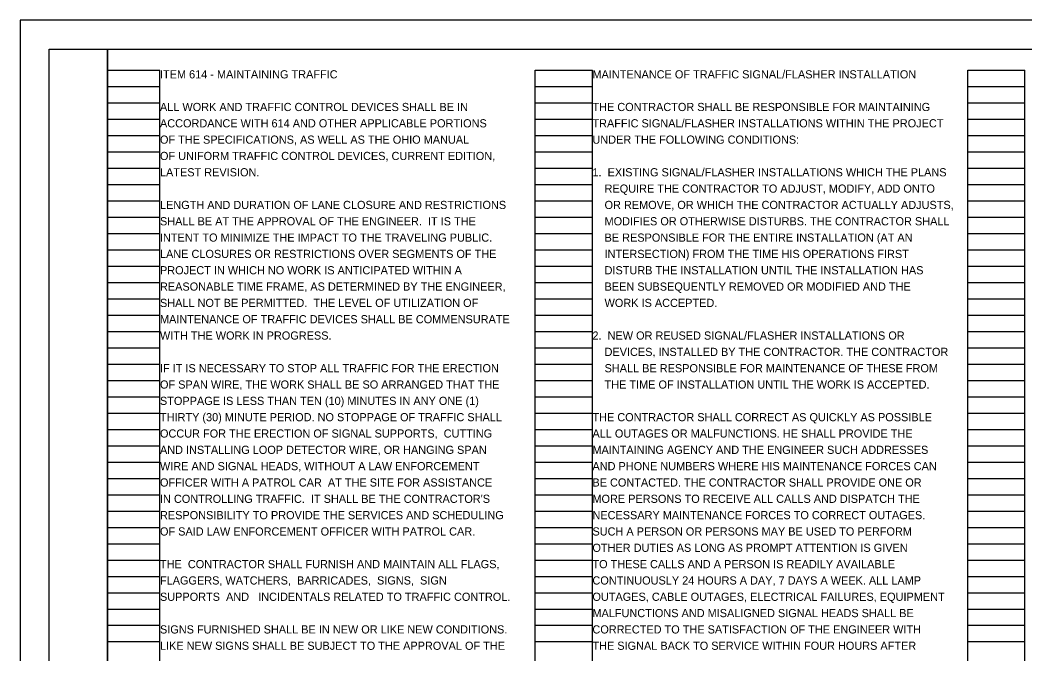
# Model space of a CAD drawing. Extents: x 0 to 34, y 0 to 22.
# Drawn here: x 0 to 17.24, y 11.13 to 22 of the extents above; entities that cross this region are included whole.
import ezdxf

# ---------------------------------------------------------------- set-up
doc = ezdxf.new("R2010")
doc.units = 0
for name, color, linetype in [('SH_Border', 7, 'Continuous'), ('SH_Cut_Line', 7, 'Continuous'), ('SH_Data', 7, 'Continuous'), ('SH_Text', 7, 'Continuous')]:
    doc.layers.add(name, color=color, linetype=linetype)

msp = doc.modelspace()

# ---------------------------------------------------------------- linework, layer by layer
at = {"layer": 'SH_Border'}
for points in [[(0.5, 21.5), (1.5, 21.5), (1.5, 0.5), (0.5, 0.5)], [(1.5, 21.5), (33.5, 21.5), (33.5, 0.5), (1.5, 0.5)]]:
    msp.add_lwpolyline(points, close=True, dxfattribs=at)
at = {"layer": 'SH_Cut_Line'}
msp.add_lwpolyline([(0, 0), (34, 0), (34, 22), (0, 22)], close=True, dxfattribs=at)
at = {"layer": 'SH_Data'}
for p, q in [((1.5, 0.98), (1.5, 21.14)), ((1.5, 21.14), (2.4, 21.14)), ((2.4, 0.98), (2.4, 21.14)), ((8.84, 0.98), (8.84, 21.14)), ((8.84, 21.14), (9.82, 21.14)), ((9.82, 0.98), (9.82, 21.14)), ((16.26, 0.98), (16.26, 21.14)), ((16.26, 21.14), (17.24, 21.14)), ((17.24, 0.98), (17.24, 21.14)), ((1.5, 20.86), (2.4, 20.86)), ((8.84, 20.86), (9.82, 20.86)), ((16.26, 20.86), (17.24, 20.86)), ((1.5, 20.58), (2.4, 20.58)), ((8.84, 20.58), (9.82, 20.58)), ((16.26, 20.58), (17.24, 20.58)), ((1.5, 20.3), (2.4, 20.3)), ((8.84, 20.3), (9.82, 20.3)), ((16.26, 20.3), (17.24, 20.3)), ((1.5, 20.02), (2.4, 20.02)), ((8.84, 20.02), (9.82, 20.02)), ((16.26, 20.02), (17.24, 20.02)), ((1.5, 19.74), (2.4, 19.74)), ((8.84, 19.74), (9.82, 19.74)), ((16.26, 19.74), (17.24, 19.74)), ((1.5, 19.46), (2.4, 19.46)), ((8.84, 19.46), (9.82, 19.46)), ((16.26, 19.46), (17.24, 19.46)), ((1.5, 19.18), (2.4, 19.18)), ((8.84, 19.18), (9.82, 19.18)), ((16.26, 19.18), (17.24, 19.18)), ((1.5, 18.9), (2.4, 18.9)), ((8.84, 18.9), (9.82, 18.9)), ((16.26, 18.9), (17.24, 18.9)), ((1.5, 18.62), (2.4, 18.62)), ((8.84, 18.62), (9.82, 18.62)), ((16.26, 18.62), (17.24, 18.62)), ((1.5, 18.34), (2.4, 18.34)), ((8.84, 18.34), (9.82, 18.34)), ((16.26, 18.34), (17.24, 18.34)), ((1.5, 18.06), (2.4, 18.06)), ((8.84, 18.06), (9.82, 18.06)), ((16.26, 18.06), (17.24, 18.06)), ((1.5, 17.78), (2.4, 17.78)), ((8.84, 17.78), (9.82, 17.78)), ((16.26, 17.78), (17.24, 17.78)), ((1.5, 17.5), (2.4, 17.5)), ((8.84, 17.5), (9.82, 17.5)), ((16.26, 17.5), (17.24, 17.5)), ((1.5, 17.22), (2.4, 17.22)), ((8.84, 17.22), (9.82, 17.22)), ((16.26, 17.22), (17.24, 17.22)), ((1.5, 16.94), (2.4, 16.94)), ((8.84, 16.94), (9.82, 16.94)), ((16.26, 16.94), (17.24, 16.94)), ((1.5, 16.66), (2.4, 16.66)), ((8.84, 16.66), (9.82, 16.66)), ((16.26, 16.66), (17.24, 16.66)), ((1.5, 16.38), (2.4, 16.38)), ((8.84, 16.38), (9.82, 16.38)), ((16.26, 16.38), (17.24, 16.38)), ((1.5, 16.1), (2.4, 16.1)), ((8.84, 16.1), (9.82, 16.1)), ((16.26, 16.1), (17.24, 16.1)), ((1.5, 15.82), (2.4, 15.82)), ((8.84, 15.82), (9.82, 15.82)), ((16.26, 15.82), (17.24, 15.82)), ((1.5, 15.54), (2.4, 15.54)), ((8.84, 15.54), (9.82, 15.54)), ((16.26, 15.54), (17.24, 15.54)), ((1.5, 15.26), (2.4, 15.26)), ((8.84, 15.26), (9.82, 15.26)), ((16.26, 15.26), (17.24, 15.26)), ((1.5, 14.98), (2.4, 14.98)), ((8.84, 14.98), (9.82, 14.98)), ((16.26, 14.98), (17.24, 14.98)), ((1.5, 14.7), (2.4, 14.7)), ((8.84, 14.7), (9.82, 14.7)), ((16.26, 14.7), (17.24, 14.7)), ((1.5, 14.42), (2.4, 14.42)), ((8.84, 14.42), (9.82, 14.42)), ((16.26, 14.42), (17.24, 14.42)), ((1.5, 14.14), (2.4, 14.14)), ((8.84, 14.14), (9.82, 14.14)), ((16.26, 14.14), (17.24, 14.14)), ((1.5, 13.86), (2.4, 13.86)), ((8.84, 13.86), (9.82, 13.86)), ((16.26, 13.86), (17.24, 13.86)), ((1.5, 13.58), (2.4, 13.58)), ((8.84, 13.58), (9.82, 13.58)), ((16.26, 13.58), (17.24, 13.58)), ((1.5, 13.3), (2.4, 13.3)), ((8.84, 13.3), (9.82, 13.3)), ((16.26, 13.3), (17.24, 13.3)), ((1.5, 13.02), (2.4, 13.02)), ((8.84, 13.02), (9.82, 13.02)), ((16.26, 13.02), (17.24, 13.02)), ((1.5, 12.74), (2.4, 12.74)), ((8.84, 12.74), (9.82, 12.74)), ((16.26, 12.74), (17.24, 12.74)), ((1.5, 12.46), (2.4, 12.46)), ((8.84, 12.46), (9.82, 12.46)), ((16.26, 12.46), (17.24, 12.46)), ((1.5, 12.18), (2.4, 12.18)), ((8.84, 12.18), (9.82, 12.18)), ((16.26, 12.18), (17.24, 12.18)), ((1.5, 11.9), (2.4, 11.9)), ((8.84, 11.9), (9.82, 11.9)), ((16.26, 11.9), (17.24, 11.9)), ((1.5, 11.62), (2.4, 11.62)), ((8.84, 11.62), (9.82, 11.62)), ((16.26, 11.62), (17.24, 11.62)), ((1.5, 11.34), (2.4, 11.34)), ((8.84, 11.34), (9.82, 11.34)), ((16.26, 11.34), (17.24, 11.34))]:
    msp.add_line(p, q, dxfattribs=at)

# ---------------------------------------------------------------- texts
at = {"layer": 'SH_Text'}
for s, p in [('ITEM 614 - MAINTAINING TRAFFIC', (2.4, 21)), ('MAINTENANCE OF TRAFFIC SIGNAL/FLASHER INSTALLATION', (9.82, 21)), ('ALL WORK AND TRAFFIC CONTROL DEVICES SHALL BE IN', (2.4, 20.44)), ('THE CONTRACTOR SHALL BE RESPONSIBLE FOR MAINTAINING', (9.82, 20.44)), ('ACCORDANCE WITH 614 AND OTHER APPLICABLE PORTIONS', (2.4, 20.16)), ('TRAFFIC SIGNAL/FLASHER INSTALLATIONS WITHIN THE PROJECT', (9.82, 20.16)), ('OF THE SPECIFICATIONS, AS WELL AS THE OHIO MANUAL', (2.4, 19.88)), ('UNDER THE FOLLOWING CONDITIONS:', (9.82, 19.88)), ('OF UNIFORM TRAFFIC CONTROL DEVICES, CURRENT EDITION,', (2.4, 19.6)), ('LATEST REVISION.', (2.4, 19.32)), ('1.  EXISTING SIGNAL/FLASHER INSTALLATIONS WHICH THE PLANS', (9.82, 19.32)), ('    REQUIRE THE CONTRACTOR TO ADJUST, MODIFY, ADD ONTO', (9.82, 19.04)), ('LENGTH AND DURATION OF LANE CLOSURE AND RESTRICTIONS', (2.4, 18.76)), ('    OR REMOVE, OR WHICH THE CONTRACTOR ACTUALLY ADJUSTS,', (9.82, 18.76)), ('SHALL BE AT THE APPROVAL OF THE ENGINEER.  IT IS THE', (2.4, 18.48)), ('    MODIFIES OR OTHERWISE DISTURBS. THE CONTRACTOR SHALL', (9.82, 18.48)), ('INTENT TO MINIMIZE THE IMPACT TO THE TRAVELING PUBLIC.', (2.4, 18.2)), ('    BE RESPONSIBLE FOR THE ENTIRE INSTALLATION (AT AN', (9.82, 18.2)), ('LANE CLOSURES OR RESTRICTIONS OVER SEGMENTS OF THE', (2.4, 17.92)), ('    INTERSECTION) FROM THE TIME HIS OPERATIONS FIRST', (9.82, 17.92)), ('PROJECT IN WHICH NO WORK IS ANTICIPATED WITHIN A', (2.4, 17.64)), ('    DISTURB THE INSTALLATION UNTIL THE INSTALLATION HAS', (9.82, 17.64)), ('REASONABLE TIME FRAME, AS DETERMINED BY THE ENGINEER,', (2.4, 17.36)), ('    BEEN SUBSEQUENTLY REMOVED OR MODIFIED AND THE', (9.82, 17.36)), ('SHALL NOT BE PERMITTED.  THE LEVEL OF UTILIZATION OF', (2.4, 17.08)), ('    WORK IS ACCEPTED.', (9.82, 17.08)), ('MAINTENANCE OF TRAFFIC DEVICES SHALL BE COMMENSURATE', (2.4, 16.8)), ('WITH THE WORK IN PROGRESS.', (2.4, 16.52)), ('2.  NEW OR REUSED SIGNAL/FLASHER INSTALLATIONS OR', (9.82, 16.52)), ('    DEVICES, INSTALLED BY THE CONTRACTOR. THE CONTRACTOR', (9.82, 16.24)), ('IF IT IS NECESSARY TO STOP ALL TRAFFIC FOR THE ERECTION', (2.4, 15.96)), ('    SHALL BE RESPONSIBLE FOR MAINTENANCE OF THESE FROM', (9.82, 15.96)), ('OF SPAN WIRE, THE WORK SHALL BE SO ARRANGED THAT THE', (2.4, 15.68)), ('    THE TIME OF INSTALLATION UNTIL THE WORK IS ACCEPTED.', (9.82, 15.68)), ('STOPPAGE IS LESS THAN TEN (10) MINUTES IN ANY ONE (1)', (2.4, 15.4)), ('THIRTY (30) MINUTE PERIOD. NO STOPPAGE OF TRAFFIC SHALL', (2.4, 15.12)), ('THE CONTRACTOR SHALL CORRECT AS QUICKLY AS POSSIBLE', (9.82, 15.12)), ('OCCUR FOR THE ERECTION OF SIGNAL SUPPORTS,  CUTTING', (2.4, 14.84)), ('ALL OUTAGES OR MALFUNCTIONS. HE SHALL PROVIDE THE', (9.82, 14.84)), ('AND INSTALLING LOOP DETECTOR WIRE, OR HANGING SPAN', (2.4, 14.56)), ('MAINTAINING AGENCY AND THE ENGINEER SUCH ADDRESSES', (9.82, 14.56)), ('WIRE AND SIGNAL HEADS, WITHOUT A LAW ENFORCEMENT', (2.4, 14.28)), ('AND PHONE NUMBERS WHERE HIS MAINTENANCE FORCES CAN', (9.82, 14.28)), ('OFFICER WITH A PATROL CAR  AT THE SITE FOR ASSISTANCE', (2.4, 14)), ('BE CONTACTED. THE CONTRACTOR SHALL PROVIDE ONE OR', (9.82, 14)), ("IN CONTROLLING TRAFFIC.  IT SHALL BE THE CONTRACTOR'S", (2.4, 13.72)), ('MORE PERSONS TO RECEIVE ALL CALLS AND DISPATCH THE', (9.82, 13.72)), ('RESPONSIBILITY TO PROVIDE THE SERVICES AND SCHEDULING', (2.4, 13.44)), ('NECESSARY MAINTENANCE FORCES TO CORRECT OUTAGES.', (9.82, 13.44)), ('OF SAID LAW ENFORCEMENT OFFICER WITH PATROL CAR.', (2.4, 13.16)), ('SUCH A PERSON OR PERSONS MAY BE USED TO PERFORM', (9.82, 13.16)), ('OTHER DUTIES AS LONG AS PROMPT ATTENTION IS GIVEN', (9.82, 12.88)), ('THE  CONTRACTOR SHALL FURNISH AND MAINTAIN ALL FLAGS,', (2.4, 12.6)), ('TO THESE CALLS AND A PERSON IS READILY AVAILABLE', (9.82, 12.6)), ('FLAGGERS, WATCHERS,  BARRICADES,  SIGNS,  SIGN', (2.4, 12.32)), ('CONTINUOUSLY 24 HOURS A DAY, 7 DAYS A WEEK. ALL LAMP', (9.82, 12.32)), ('SUPPORTS  AND   INCIDENTALS RELATED TO TRAFFIC CONTROL.', (2.4, 12.04)), ('OUTAGES, CABLE OUTAGES, ELECTRICAL FAILURES, EQUIPMENT', (9.82, 12.04)), ('MALFUNCTIONS AND MISALIGNED SIGNAL HEADS SHALL BE', (9.82, 11.76)), ('SIGNS FURNISHED SHALL BE IN NEW OR LIKE NEW CONDITIONS.', (2.4, 11.48)), ('CORRECTED TO THE SATISFACTION OF THE ENGINEER WITH', (9.82, 11.48)), ('LIKE NEW SIGNS SHALL BE SUBJECT TO THE APPROVAL OF THE', (2.4, 11.2)), ('THE SIGNAL BACK TO SERVICE WITHIN FOUR HOURS AFTER', (9.82, 11.2))]:
    msp.add_text(s, height=0.14, dxfattribs=at).set_placement(p)

doc.saveas('drawing.dxf')
